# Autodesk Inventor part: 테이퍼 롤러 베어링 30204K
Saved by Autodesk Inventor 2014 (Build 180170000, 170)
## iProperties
Created: 2026-01
Part Number: 테이퍼 롤러 베어링 30204K
Material: 일반
Document SubType Name: Modeling
Designer: dg
Density: 1 g/cm^3
Appearance: 기본값
Author: dg
Author: jhkim
Description: 테이퍼 롤러 베어링
Creation Date: 2026-01-09
Sending System: Autodesk Inventor 2026
Preprocessor: ST-DEVELOPER v20.1
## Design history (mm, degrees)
node "테이퍼 롤러 베어링 30204K1"
body "Solid1"
node "Solid1_1"
node "기준1"
node "기준2"
